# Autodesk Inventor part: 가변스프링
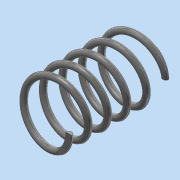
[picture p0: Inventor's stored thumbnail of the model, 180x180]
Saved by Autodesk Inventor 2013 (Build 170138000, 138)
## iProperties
Created: 2017-12
Part Number: 가변스프링
Material: 스테인리스강
Document SubType Name: Modeling
Designer: dgall
Mass: 7.0703 g
Surface Area: 17.7407 cm^2
Volume: 0.875038 cm^3
Density: 8.08 g/cm^3
Author: dgall
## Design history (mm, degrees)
sketch "스케치1"
  geometry: L1 (0, 0)-(0, 28.5); L2 (0, 28.5)-(9, 28.5); L3 (0, 0)-(9, 0); C1 r 1 at (9, 0)
  constraints: 6 end point, 2 parallel, 1 centre point, 1 coincident, 1 perpendicular, 1 vertical
  dimensions: "d0" = 28.49996 distance of L1.start L1.end (derived); "d1" = 18 diameter of L3.end L1; "d2" = 2 diameter of C1
feature "코일1" sketch "스케치1" pitch "d3" = 10; turns "d5" = 5; dims "d4" = 28.49996 (= d0), "d6" = 0, angle "d7" = 90 deg, angle "d8" = 90 deg, "d9" = 0, "d10" = 0
node "작업 평면1"
node "작업 평면2"
feature "분할1"
feature "분할2"
node "솔리드1"
